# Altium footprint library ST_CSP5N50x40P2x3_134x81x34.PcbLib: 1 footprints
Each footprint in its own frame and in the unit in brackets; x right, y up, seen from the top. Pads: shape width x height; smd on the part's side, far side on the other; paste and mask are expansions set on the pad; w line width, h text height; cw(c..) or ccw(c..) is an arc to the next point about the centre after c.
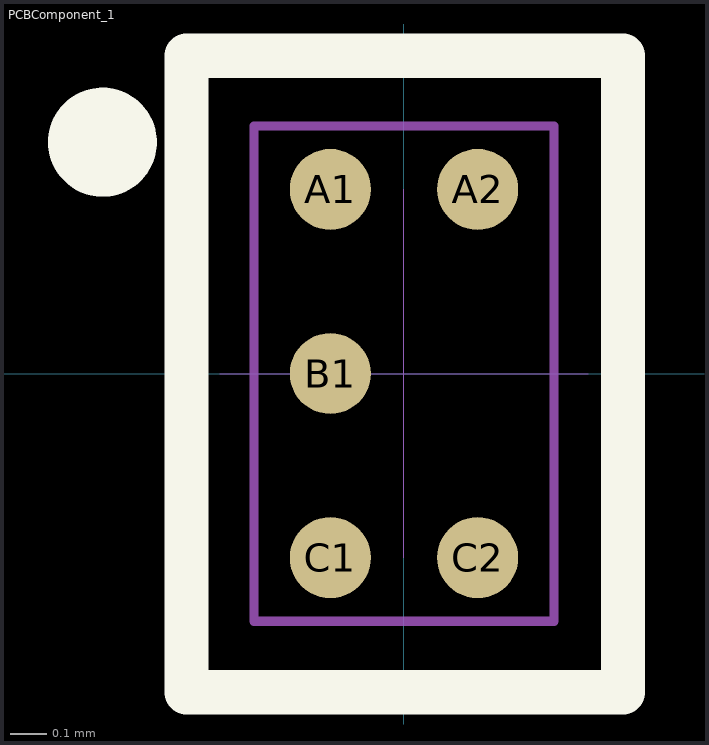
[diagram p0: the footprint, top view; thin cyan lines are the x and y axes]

## PCBComponent_1 [mm]
pads (5):
  round 0.22 smd paste-20 mask+0.05: A1(-0.2,0.5) A2(0.2,0.5) B1(-0.2,0) C1(-0.2,-0.5) C2(0.2,-0.5)
Top Overlay:
  circle w0.2: c-0.819,0.628 r0.048
  lines w0.12: -0.591,-0.865 0.595,-0.865 0.595,0.863 -0.591,0.863 -0.591,-0.865
Top Paste:
  rectangle: 0.09,-0.61 0.31,-0.39
  rectangle: -0.31,-0.61 -0.09,-0.39
  rectangle: -0.31,-0.11 -0.09,0.11
  rectangle: 0.09,0.39 0.31,0.61
  rectangle: -0.31,0.39 -0.09,0.61
Mechanical 15:
  lines w0: 0.407,-0.673 0.407,-0.142
  lines w0.001: -0.5,0 0.5,0 ; 0,-0.5 0,0.5
  lines w0.025: -0.407,-0.673 0.407,-0.673 0.407,0.673 -0.407,0.673 -0.407,-0.673
3D body: height 0.38, standoff 0.12, extent -0.407,-0.673 0.407,0.673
